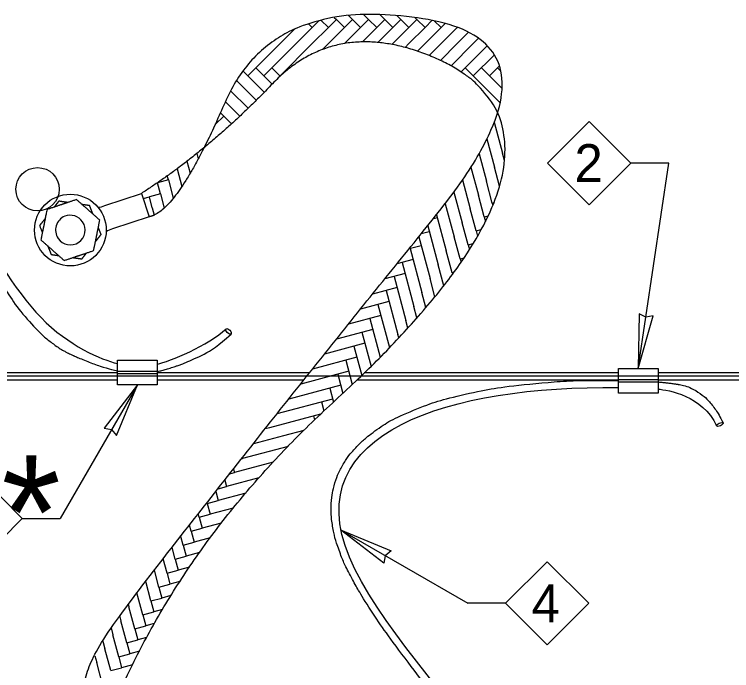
# Model space of a CAD drawing. Extents: x 99862 to 103680, y 99470 to 102076.
# Drawn here: x 101447.7 to 101750, y 101521 to 101797.8 of the extents above; entities that cross this region are included whole.
import ezdxf

# ---------------------------------------------------------------- set-up
doc = ezdxf.new("R2010")
doc.units = 0
for name, color, linetype in [('Level 10', 7, 'Continuous'), ('Level 11', 7, 'Continuous'), ('Level 13', 7, 'Continuous'), ('Level 15', 7, 'Continuous'), ('Level 20', 7, 'Continuous'), ('Level 3', 7, 'Continuous'), ('Level 9', 7, 'Continuous')]:
    doc.layers.add(name, color=color, linetype=linetype)

msp = doc.modelspace()

# ---------------------------------------------------------------- linework, layer by layer
at = {"layer": 'Level 10'}
for p, q in [((101476.44, 101710.32), (101476.44, 101710.32)), ((101466.11, 101703.3), (101466.11, 101703.3))]:
    msp.add_line(p, q, dxfattribs=at)
msp.add_circle((101457.48, 101723.99), 9.15, dxfattribs=at)
for start, end in [(111.8062, 214.2159), (214.2159, 34.2159), (34.2159, 111.8062)]:
    msp.add_arc((101471.27, 101706.81), 6.25, start, end, dxfattribs=at)
for points in [[(101473.87, 101719.65), (101469.73, 101718.26), (101465.59, 101716.87), (101461.45, 101715.48)], [(101483.69, 101710.98), (101480.42, 101713.87), (101477.14, 101716.76), (101473.87, 101719.65)], [(101466.41, 101718.98), (101465.75, 101718.15), (101465.1, 101717.32), (101464.45, 101716.49)], [(101470.22, 101718.43), (101468.95, 101718.61), (101467.68, 101718.79), (101466.41, 101718.98)], [(101479.37, 101717.11), (101478.33, 101717.26), (101477.29, 101717.41), (101476.24, 101717.56)], [(101480.81, 101713.53), (101480.33, 101714.72), (101479.85, 101715.92), (101479.38, 101717.11)], [(101461.45, 101715.48), (101460.39, 101710.26), (101459.62, 101706.44), (101458.85, 101702.64)], [(101460.69, 101711.71), (101459.89, 101710.7), (101459.1, 101709.69), (101458.3, 101708.68)], [(101481.1, 101698.14), (101481.96, 101702.42), (101482.83, 101706.7), (101483.69, 101710.98)], [(101458.3, 101708.68), (101459.05, 101706.81), (101459.27, 101706.28), (101459.48, 101705.74)], [(101484.24, 101704.94), (101483.85, 101705.92), (101483.46, 101706.9), (101483.07, 101707.88)], [(101481.86, 101701.92), (101482.66, 101702.93), (101483.45, 101703.93), (101484.24, 101704.94)], [(101458.85, 101702.64), (101462.13, 101699.75), (101465.4, 101696.86), (101468.68, 101693.97)], [(101461.74, 101700.09), (101462.22, 101698.9), (101462.7, 101697.7), (101463.17, 101696.51)], [(101468.68, 101693.97), (101472.82, 101695.36), (101476.96, 101696.75), (101481.1, 101698.14)], [(101463.17, 101696.51), (101464.22, 101696.36), (101465.26, 101696.21), (101466.3, 101696.06)], [(101472.33, 101695.19), (101473.6, 101695.01), (101474.87, 101694.83), (101476.14, 101694.65)], [(101476.14, 101694.65), (101476.79, 101695.47), (101477.44, 101696.3), (101478.1, 101697.13)]]:
    msp.add_open_spline(points, degree=2, dxfattribs=at)
at = {"layer": 'Level 11'}
for p, q in [((101573.23, 101792.18), (101576.19, 101795.14)), ((101580.02, 101792.18), (101576.89, 101795.31)), ((101580.02, 101792.18), (101583.41, 101795.57)), ((101582.51, 101796.48), (101583.41, 101795.57)), ((101586.81, 101792.18), (101583.41, 101795.58)), ((101586.81, 101792.18), (101590.2, 101795.57)), ((101588.5, 101797.28), (101590.2, 101795.57)), ((101593.6, 101792.18), (101590.2, 101795.58)), ((101593.6, 101792.18), (101596.99, 101795.57)), ((101594.88, 101797.68), (101596.99, 101795.57)), ((101600.38, 101792.18), (101596.99, 101795.58)), ((101600.38, 101792.18), (101603.78, 101795.57)), ((101601.67, 101797.69), (101603.78, 101795.57)), ((101607.17, 101792.18), (101603.78, 101795.58)), ((101607.17, 101792.18), (101610.57, 101795.57)), ((101608.87, 101797.27), (101610.57, 101795.57)), ((101613.96, 101792.18), (101610.57, 101795.58)), ((101613.96, 101792.18), (101617.36, 101795.57)), ((101616.51, 101796.42), (101617.36, 101795.57)), ((101620.75, 101792.18), (101617.36, 101795.58)), ((101620.75, 101792.18), (101623.79, 101795.23)), ((101627.54, 101792.18), (101624.67, 101795.05)), ((101573.23, 101792.18), (101566.44, 101785.39)), ((101573.23, 101792.18), (101571.63, 101793.78)), ((101580.02, 101792.18), (101573.23, 101785.39)), ((101586.81, 101792.18), (101580.02, 101785.39)), ((101593.6, 101792.18), (101586.85, 101785.44)), ((101600.38, 101792.18), (101594.34, 101786.14)), ((101607.17, 101792.18), (101600.89, 101785.89)), ((101607.17, 101792.18), (101607.17, 101792.18)), ((101613.96, 101792.18), (101607.17, 101785.39)), ((101620.75, 101792.18), (101613.96, 101785.39)), ((101627.54, 101792.18), (101620.75, 101785.39)), ((101627.54, 101792.18), (101629.29, 101793.93)), ((101634.32, 101792.18), (101627.54, 101785.39)), ((101634.33, 101792.18), (101634.12, 101792.39)), ((101634.33, 101792.18), (101634.42, 101792.27)), ((101565.72, 101791.46), (101559.66, 101785.39)), ((101639.13, 101790.2), (101634.33, 101785.39)), ((101643.36, 101787.64), (101641.11, 101785.39)), ((101546.08, 101771.82), (101559.66, 101785.39)), ((101552.87, 101771.82), (101566.44, 101785.39)), ((101559.66, 101771.82), (101573.23, 101785.39)), ((101577.56, 101782.93), (101580.02, 101785.39)), ((101606.83, 101785.05), (101607.17, 101785.39)), ((101607.17, 101785.39), (101607.17, 101785.39)), ((101612.37, 101783.8), (101613.96, 101785.39)), ((101617.58, 101782.22), (101620.75, 101785.39)), ((101622.53, 101780.39), (101627.54, 101785.39)), ((101627.26, 101778.33), (101634.33, 101785.39)), ((101631.75, 101776.03), (101641.11, 101785.39)), ((101635.97, 101773.46), (101647.02, 101784.51)), ((101641.11, 101771.82), (101650, 101780.71)), ((101544.02, 101773.87), (101552.97, 101764.93)), ((101549.47, 101775.21), (101556.33, 101768.36)), ((101556.26, 101775.21), (101559.75, 101771.72)), ((101563.05, 101775.21), (101563.42, 101774.84)), ((101637.72, 101775.21), (101652.42, 101760.51)), ((101644.51, 101775.21), (101653.26, 101766.46)), ((101647.9, 101771.82), (101652.15, 101776.06)), ((101651.3, 101775.21), (101652.77, 101773.74)), ((101541.28, 101769.83), (101549.61, 101761.5)), ((101538.8, 101765.52), (101546.16, 101758.16)), ((101536.6, 101760.93), (101542.69, 101754.85)), ((101534.5, 101756.24), (101535.9, 101754.85)), ((101532.5, 101751.45), (101535.9, 101754.85)), ((101539.15, 101751.59), (101535.9, 101754.85)), ((101542.09, 101754.25), (101542.69, 101754.85)), ((101542.7, 101754.83), (101542.69, 101754.85)), ((101532.5, 101751.45), (101532.25, 101751.2)), ((101532.5, 101751.45), (101532.41, 101751.55)), ((101649.92, 101752.27), (101653.42, 101739.21)), ((101646.84, 101745.23), (101650.03, 101733.34)), ((101524.54, 101739.03), (101525.14, 101736.78)), ((101643.54, 101739), (101646.63, 101727.46)), ((101654.26, 101736.09), (101653.42, 101739.21)), ((101520.43, 101735.81), (101521.78, 101730.78)), ((101516.3, 101732.68), (101518.3, 101725.22)), ((101640.09, 101733.32), (101643.24, 101721.58)), ((101652.18, 101725.29), (101650.03, 101733.34)), ((101512.61, 101727.93), (101512.15, 101729.65)), ((101507.9, 101726.67), (101507.97, 101726.69)), ((101512.61, 101727.93), (101507.97, 101726.69)), ((101509.21, 101722.05), (101507.97, 101726.69)), ((101512.61, 101727.93), (101514.67, 101720.23)), ((101636.56, 101727.95), (101639.84, 101715.7)), ((101649.12, 101718.18), (101646.63, 101727.46)), ((101632.97, 101722.83), (101636.45, 101709.82)), ((101501.93, 101720.1), (101504.58, 101720.81)), ((101509.21, 101722.05), (101504.58, 101720.81)), ((101505.82, 101716.17), (101504.58, 101720.81)), ((101509.21, 101722.05), (101510.82, 101716.06)), ((101509.21, 101722.05), (101509.21, 101722.05)), ((101645.72, 101712.31), (101643.24, 101721.58)), ((101505.82, 101716.17), (101506.64, 101713.11)), ((101629.33, 101717.85), (101629.25, 101717.83)), ((101629.31, 101717.92), (101630.57, 101713.22)), ((101649.12, 101718.18), (101649.84, 101718.38)), ((101649.12, 101718.18), (101649.37, 101717.24)), ((101625.6, 101713.21), (101629.66, 101698.06)), ((101630.57, 101713.22), (101633.06, 101703.94)), ((101642.33, 101706.43), (101639.84, 101715.7)), ((101625.94, 101711.97), (101624.28, 101711.53)), ((101645.72, 101712.31), (101647.4, 101712.75)), ((101645.72, 101712.31), (101646.24, 101710.37)), ((101621.88, 101708.55), (101626.27, 101692.18)), ((101638.94, 101700.55), (101636.45, 101709.82)), ((101636.45, 101709.82), (101636.45, 101709.82)), ((101622.54, 101706.09), (101619.17, 101705.19)), ((101642.33, 101706.43), (101644.46, 101707)), ((101642.33, 101706.43), (101642.33, 101706.43)), ((101642.33, 101706.43), (101642.91, 101704.24)), ((101618.15, 101703.93), (101622.87, 101686.31)), ((101635.54, 101694.67), (101633.06, 101703.94)), ((101638.94, 101700.55), (101641.07, 101701.12)), ((101619.15, 101700.22), (101614.05, 101698.85)), ((101614.51, 101698.97), (101619.48, 101680.43)), ((101632.15, 101688.79), (101629.66, 101698.06)), ((101638.94, 101700.55), (101639.47, 101698.55)), ((101635.54, 101694.67), (101637.22, 101695.12)), ((101615.75, 101694.34), (101608.93, 101692.51)), ((101611.12, 101693.09), (101616.09, 101674.55)), ((101628.65, 101683.31), (101626.27, 101692.18)), ((101635.54, 101694.67), (101635.93, 101693.22)), ((101632.15, 101688.79), (101632.93, 101689)), ((101612.36, 101688.46), (101603.8, 101686.17)), ((101607.72, 101687.22), (101612.69, 101668.67)), ((101624.93, 101678.64), (101622.87, 101686.31)), ((101632.15, 101688.79), (101632.32, 101688.16)), ((101608.97, 101682.58), (101598.68, 101679.82)), ((101604.33, 101681.34), (101609.3, 101662.79)), ((101621.17, 101674.11), (101619.48, 101680.43)), ((101605.57, 101676.7), (101593.56, 101673.48)), ((101600.93, 101675.46), (101605.81, 101657.25)), ((101617.37, 101669.75), (101616.09, 101674.55)), ((101602.18, 101670.82), (101588.51, 101667.16)), ((101597.54, 101669.58), (101601.92, 101653.25)), ((101613.54, 101665.49), (101612.69, 101668.67)), ((101598.78, 101664.94), (101583.48, 101660.84)), ((101594.15, 101663.7), (101598, 101649.33)), ((101609.7, 101661.3), (101609.3, 101662.79)), ((101595.39, 101659.06), (101578.44, 101654.52)), ((101590.75, 101657.82), (101594.06, 101645.48)), ((101591.99, 101653.19), (101573.4, 101648.2)), ((101587.36, 101651.94), (101590.11, 101641.68)), ((101588.6, 101647.31), (101568.36, 101641.88)), ((101583.96, 101646.06), (101586.14, 101637.95)), ((101585.21, 101641.43), (101563.32, 101635.56)), ((101580.57, 101640.19), (101582.16, 101634.25)), ((101581.81, 101635.55), (101558.33, 101629.26)), ((101577.18, 101634.31), (101578.18, 101630.56)), ((101576.76, 101629.23), (101555.24, 101623.46)), ((101573.78, 101628.43), (101574.22, 101626.81)), ((101555.24, 101623.46), (101553.37, 101622.96)), ((101561.12, 101620.07), (101548.41, 101616.66)), ((101569.65, 101622.35), (101561.12, 101620.07)), ((101563.02, 101615.61), (101543.81, 101610.46)), ((101543.44, 101610.36), (101543.81, 101610.46)), ((101543.74, 101610.74), (101543.81, 101610.46)), ((101556.72, 101608.95), (101540.42, 101604.58)), ((101538.48, 101604.06), (101540.42, 101604.58)), ((101540.03, 101606.03), (101540.42, 101604.58)), ((101536.32, 101601.32), (101537.02, 101598.7)), ((101550.78, 101602.39), (101537.02, 101598.7)), ((101533.52, 101597.76), (101537.02, 101598.7)), ((101532.61, 101596.62), (101533.63, 101592.82)), ((101545.17, 101595.92), (101533.63, 101592.82)), ((101528.99, 101591.58), (101533.63, 101592.82)), ((101528.99, 101591.58), (101528.91, 101591.91)), ((101528.99, 101591.58), (101530.24, 101586.95)), ((101539.86, 101589.52), (101530.24, 101586.95)), ((101525.6, 101585.7), (101525.21, 101587.16)), ((101525.6, 101585.7), (101530.24, 101586.95)), ((101525.6, 101585.7), (101526.84, 101581.07)), ((101534.89, 101583.22), (101526.84, 101581.07)), ((101522.21, 101579.82), (101521.51, 101582.41)), ((101522.21, 101579.82), (101526.84, 101581.07)), ((101518.81, 101573.95), (101517.81, 101577.67)), ((101522.21, 101579.82), (101523.45, 101575.19)), ((101518.81, 101573.95), (101523.45, 101575.19)), ((101530.18, 101576.99), (101523.45, 101575.19)), ((101515.42, 101568.07), (101514.12, 101572.92)), ((101518.81, 101573.95), (101520.05, 101569.31)), ((101512.02, 101562.19), (101510.42, 101568.17)), ((101515.42, 101568.07), (101520.05, 101569.31)), ((101515.42, 101568.07), (101516.66, 101563.43)), ((101525.71, 101570.82), (101520.05, 101569.31)), ((101508.63, 101556.31), (101506.72, 101563.43)), ((101512.02, 101562.19), (101516.66, 101563.43)), ((101512.02, 101562.19), (101513.27, 101557.55)), ((101521.45, 101564.71), (101516.66, 101563.43)), ((101505.24, 101550.43), (101503.02, 101558.68)), ((101508.63, 101556.31), (101513.27, 101557.55)), ((101508.63, 101556.31), (101509.87, 101551.67)), ((101517.44, 101558.67), (101513.27, 101557.55)), ((101499.33, 101553.93), (101499.36, 101553.82)), ((101501.84, 101544.55), (101499.36, 101553.82)), ((101505.24, 101550.43), (101509.87, 101551.67)), ((101505.24, 101550.43), (101506.48, 101545.79)), ((101513.67, 101552.69), (101509.87, 101551.67)), ((101495.63, 101549.18), (101495.96, 101547.95)), ((101498.45, 101538.67), (101495.96, 101547.95)), ((101491.98, 101544.27), (101492.57, 101542.07)), ((101501.84, 101544.55), (101506.48, 101545.79)), ((101501.84, 101544.55), (101503.08, 101539.92)), ((101510.07, 101546.76), (101506.48, 101545.79)), ((101495.05, 101532.8), (101492.57, 101542.07)), ((101506.63, 101540.87), (101503.08, 101539.92)), ((101488.41, 101539.06), (101489.17, 101536.19)), ((101498.45, 101538.67), (101503.08, 101539.92)), ((101498.45, 101538.67), (101499.69, 101534.04)), ((101491.66, 101526.92), (101489.17, 101536.19)), ((101503.43, 101535.04), (101499.69, 101534.04)), ((101484.93, 101533.49), (101485.78, 101530.31)), ((101495.05, 101532.8), (101499.69, 101534.04)), ((101495.05, 101532.8), (101496.3, 101528.16)), ((101488.27, 101521.04), (101485.78, 101530.31)), ((101485.78, 101530.31), (101485.78, 101530.31)), ((101500.39, 101529.26), (101496.3, 101528.16)), ((101481.6, 101527.35), (101482.39, 101524.43)), ((101491.66, 101526.92), (101496.3, 101528.16)), ((101491.66, 101526.92), (101491.66, 101526.92)), ((101491.66, 101526.92), (101492.9, 101522.28)), ((101484.87, 101515.16), (101482.39, 101524.43)), ((101497.48, 101523.51), (101492.9, 101522.28)), ((101488.27, 101521.04), (101492.9, 101522.28))]:
    msp.add_line(p, q, dxfattribs=at)
for points in [[(101574.51, 101443.65), (101428.47, 101462.51), (101563.15, 101636.34), (101684.52, 101785.6), (101556.08, 101806.12), (101516.64, 101714.68), (101504.48, 101712.39)], [(101571.25, 101437.21), (101460.29, 101437.21), (101519.62, 101576.95), (101643.97, 101690.88), (101661.74, 101764.81), (101582.83, 101796.17), (101529.92, 101740.64), (101501.22, 101722.24)]]:
    msp.add_open_spline(points, degree=2, dxfattribs=at)
at = {"layer": 'Level 13'}
for p, q in [((101485.76, 101717.11), (101501.22, 101722.24)), ((101501.22, 101722.24), (101504.48, 101712.39)), ((101504.48, 101712.39), (101489.02, 101707.27))]:
    msp.add_line(p, q, dxfattribs=at)
msp.add_circle((101471.27, 101706.81), 15.11, dxfattribs=at)
for centre, start, end in [((101482.92, 101723.2), 269.6664, 295.0227), ((101490.38, 101700.69), 101.664, 126.7367)]:
    msp.add_arc(centre, 6.72, start, end, dxfattribs=at)
at = {"layer": 'Level 15'}
for p, q in [((101723.49, 101735.02), (101707.49, 101735.02)), ((101710.62, 101648.48), (101723.49, 101735.02)), ((102234.36, 101645.22), (101092.77, 101645.22)), ((101499.53, 101641.52), (101467.03, 101585.23)), ((101451.03, 101585.23), (101467.03, 101585.23)), ((101585.15, 101580.37), (101638.74, 101549.43)), ((101654.74, 101549.43), (101638.74, 101549.43))]:
    msp.add_line(p, q, dxfattribs=at)
for points in [[(101710.62, 101648.48), (101716.93, 101670.62), (101713.82, 101670.02), (101711.03, 101671.5)], [(101499.53, 101641.52), (101485.53, 101623.24), (101488.64, 101622.66), (101490.7, 101620.25)], [(101585.15, 101580.37), (101606.42, 101571.54), (101604.01, 101569.48), (101603.43, 101566.37)]]:
    msp.add_lwpolyline(points, close=True, dxfattribs=at)
at = {"layer": 'Level 20'}
for points in [[(101689.93, 101752.57), (101707.49, 101735.02), (101689.93, 101717.46), (101672.38, 101735.02)], [(101433.48, 101602.78), (101451.03, 101585.23), (101433.48, 101567.67), (101415.92, 101585.23)], [(101672.29, 101566.98), (101689.85, 101549.43), (101672.29, 101531.88), (101654.74, 101549.43)]]:
    msp.add_lwpolyline(points, close=True, dxfattribs=at)
at = {"layer": 'Level 3'}
for p, q in [((101507.88, 101647.2), (101491.18, 101647.2)), ((101507.88, 101646.25), (101491.18, 101646.25)), ((101718.98, 101643.68), (101702.27, 101643.68)), ((101718.98, 101642.73), (101702.27, 101642.73))]:
    msp.add_line(p, q, dxfattribs=at)
for points in [[(101491.18, 101646.25), (101491.18, 101652), (101507.88, 101652), (101507.88, 101646.25)], [(101702.27, 101643.68), (101702.27, 101648.48), (101718.98, 101648.48), (101718.98, 101642.73)], [(101507.88, 101646.25), (101507.88, 101641.52), (101491.18, 101641.52), (101491.18, 101646.25)], [(101702.27, 101642.73), (101702.27, 101643.68)], [(101718.98, 101642.73), (101718.98, 101638), (101702.27, 101638), (101702.27, 101642.73)]]:
    msp.add_lwpolyline(points, dxfattribs=at)
at = {"layer": 'Level 9'}
for p, q in [((101491.18, 101646.54), (101372.94, 101646.54)), ((101572.03, 101646.54), (101507.88, 101646.54)), ((101702.27, 101646.54), (101595.18, 101646.54)), ((101937.76, 101646.54), (101718.98, 101646.54)), ((101491.18, 101643.54), (101377.94, 101643.54)), ((101569.65, 101643.54), (101507.88, 101643.54)), ((101702.27, 101643.54), (101592.08, 101643.54)), ((101800.16, 101643.54), (101718.98, 101643.54))]:
    msp.add_line(p, q, dxfattribs=at)
for centre, major_axis, ratio in [((101537.96, 101664.06), (-1.03, 1.09), 0.484572), ((101745, 101624.85), (-1.36, -0.63), 0.394772)]:
    msp.add_ellipse(centre, major_axis=major_axis, ratio=ratio, dxfattribs=at)
for points, degree in [([(101350.96, 101655.63), (101351.42, 101686.71), (101356.33, 101724.08), (101403.78, 101740.06), (101427.58, 101718.38), (101457.07, 101663.64), (101484.15, 101652.23), (101491.18, 101650.49)], 3), ([(101353.96, 101655.63), (101354.07, 101663.13), (101354.26, 101669.99), (101354.74, 101681.63), (101355.03, 101686.56), (101355.54, 101693.2), (101355.72, 101695.29), (101356.02, 101698.24), (101356.17, 101699.66), (101356.36, 101701.24), (101356.46, 101702.01), (101356.51, 101702.39), (101356.53, 101702.55), (101356.54, 101702.66), (101356.55, 101702.72), (101356.98, 101705.99), (101357.8, 101708.91), (101360.2, 101714.24), (101361.79, 101716.64), (101365.78, 101721), (101368.2, 101722.96), (101372.49, 101725.57), (101374.03, 101726.39), (101376.52, 101727.52), (101377.38, 101727.88), (101378.71, 101728.4), (101379.38, 101728.66), (101380.08, 101728.91), (101380.54, 101729.07), (101380.77, 101729.15), (101384.83, 101730.52), (101388.38, 101731.41), (101394.91, 101732.44), (101397.89, 101732.58), (101403.28, 101732.15), (101405.68, 101731.58), (101408.93, 101730.25), (101409.95, 101729.72), (101411.4, 101728.8), (101411.87, 101728.47), (101412.55, 101727.95), (101412.89, 101727.67), (101413.28, 101727.34), (101413.47, 101727.18), (101413.55, 101727.1), (101413.61, 101727.05), (101413.63, 101727.03), (101417.39, 101723.61), (101421.48, 101718.78), (101428.01, 101709.41), (101430.26, 101705.94), (101433.72, 101700.2), (101434.89, 101698.2), (101436.67, 101695.07), (101437.57, 101693.47), (101438.62, 101691.55), (101439.15, 101690.57), (101439.38, 101690.15), (101439.53, 101689.87), (101439.61, 101689.73), (101444.69, 101680.3), (101449.92, 101672.65), (101458.2, 101663.65), (101461.04, 101661.07), (101465.41, 101657.82), (101466.89, 101656.84), (101469.14, 101655.54), (101469.9, 101655.13), (101471.04, 101654.56), (101471.61, 101654.28), (101472.29, 101653.98), (101472.62, 101653.83), (101472.77, 101653.77), (101472.86, 101653.73), (101472.91, 101653.71), (101478.72, 101651.26), (101483.78, 101649.42), (101489.22, 101647.89), (101490.21, 101647.63), (101491.18, 101647.4)], 3), ([(101507.88, 101650.25), (101512.96, 101651.37), (101529.62, 101658.24), (101536.93, 101665.15)], 3), ([(101507.88, 101647.18), (101508.32, 101647.27), (101508.75, 101647.37), (101510.89, 101647.87), (101512.63, 101648.36), (101515.3, 101649.24), (101516.2, 101649.55), (101518.03, 101650.23), (101518.95, 101650.59), (101527.42, 101654.09), (101533.81, 101658.08), (101538.99, 101662.97)], 3), ([(101630.35, 101433.48), (101635.79, 101433.48), (101640.41, 101433.82), (101648.11, 101435.08), (101651.19, 101436), (101654.76, 101437.68), (101655.77, 101438.28), (101657.48, 101439.56), (101658.18, 101440.23), (101659.34, 101441.65), (101659.8, 101442.38), (101660.51, 101443.97), (101660.77, 101444.82), (101661.1, 101446.66), (101661.18, 101447.66), (101661.12, 101449.81), (101660.99, 101450.96), (101660.29, 101454.62), (101659.42, 101457.35), (101656.94, 101463.21), (101655.35, 101466.35), (101651.56, 101472.94), (101649.38, 101476.39), (101642.17, 101487.11), (101636.49, 101494.71), (101624.55, 101510.32), (101618.29, 101518.33), (101606.35, 101534.25), (101600.66, 101542.17), (101593.42, 101553.66), (101591.22, 101557.42), (101587.39, 101564.78), (101585.76, 101568.37), (101583.23, 101575.37), (101582.33, 101578.75), (101581.26, 101585.28), (101581.08, 101588.44), (101581.43, 101594.5), (101581.95, 101597.41), (101583.65, 101602.95), (101584.83, 101605.58), (101587.77, 101610.54), (101589.53, 101612.86), (101593.57, 101617.21), (101595.84, 101619.24), (101603.34, 101624.9), (101609.24, 101628.11), (101622.48, 101633.57), (101629.82, 101635.81), (101645.62, 101639.41), (101654.08, 101640.76), (101675.42, 101643.05), (101688.69, 101643.58), (101702.27, 101643.37)], 3), ([(101630.35, 101430.48), (101719.34, 101430.48), (101502.28, 101601.88), (101631.54, 101641.46), (101702.27, 101640.37)], 3), ([(101718.98, 101642.76), (101719.5, 101642.72), (101720.02, 101642.67), (101722.01, 101642.48), (101723.41, 101642.33), (101725.37, 101642.07), (101726.01, 101641.99), (101726.78, 101641.87), (101726.93, 101641.85), (101727.26, 101641.79), (101727.75, 101641.71), (101728.24, 101641.61), (101731.16, 101640.95), (101733.59, 101639.93), (101738.01, 101637.09), (101740, 101635.26), (101743.51, 101630.89), (101745.04, 101628.35), (101746.36, 101625.48)], 3), ([(101718.98, 101639.75), (101723.22, 101639.39), (101737.72, 101637.11), (101743.63, 101624.23)], 3), ([(101718.98, 101639.75), (101719.05, 101639.75), (101719.12, 101639.75), (101719.19, 101639.74)], 2)]:
    msp.add_open_spline(points, degree=degree, dxfattribs=at)

# ---------------------------------------------------------------- texts
at = {"layer": 'Level 20'}
for s, height, p in [('2', 16, (101683.76, 101727.02)), ('*', 48, (101442.25, 101563.82)), ('4', 16, (101665.7, 101541.43))]:
    msp.add_text(s, height=height, dxfattribs=at).set_placement(p)

doc.saveas('drawing.dxf')
